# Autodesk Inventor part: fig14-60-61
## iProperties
Shininess: 77.0
Angle Display Precision: 2
Document Length Units: 11269
Document Angle Units: 11279
Document Time Units: 11290
Document Mass Units: 11283
Document Length Units Precision: 3
Document Angle Units Precision: 2
Created: 2002-04
Part Number: fig14-60-61
Document SubType Name: Sheet Metal
Density: 0.0
Volumn: 0.0
Area: 0.0
PropertySet Name: Model Information
Control State: 0
Master: False
Checked Out: False
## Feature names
1. Plate1
2. Plate6
3. Bend5
4. Plate7
5. Bend7
6. Cut1
